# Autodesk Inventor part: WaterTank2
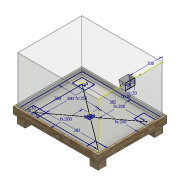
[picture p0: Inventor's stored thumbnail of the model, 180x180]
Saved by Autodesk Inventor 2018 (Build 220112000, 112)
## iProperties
Created: 2018-05
Part Number: WaterTank2
Material: Generic
Document SubType Name: Modeling
Designer: arivu
Density: 1 g/cm^3
Appearance: Default
Author: arivu
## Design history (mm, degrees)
workplane "Work Plane2"
workplane "Work Plane4"
sketch "Sketch1"
  geometry: L1 (-250, 200)-(250, 200); L2 (250, 200)-(250, -200); L3 (250, -200)-(-250, -200); L4 (-250, -200)-(-250, 200); 1 further point
  constraints: 8 end point, 2 parallel, 1 horizontal, 1 perpendicular
  dimensions: "d0" = 250 distance from line of point (0, 0) L4 (= 0.5 x width); "d1" = 250 distance from line of L2 point (0, 0) (= d0); "d2" = 200 distance from line of L3 point (0, 0) (= 0.5 x height); "d3" = 200 distance from line of L1 point (0, 0) (= d2)
extrude "Extrusion1" new body sketch "Sketch1" distance "d4" = 300 (= depth); taper "d5" = 0 deg
sketch "Sketch2"
  geometry: L1 (-250, 200)-(250, 200) reference; L2 (250, -200)-(-250, -200); L3 (-250, -200)-(-250, 200); L4 (-250, 200)-(250, 200); L5 (250, 200)-(250, -200); L6 (262, -212)-(-262, -212); L7 (-262, -212)-(-262, 212); L8 (-262, 212)-(262, 212); L9 (262, 212)-(262, -212); 1 further point
  constraints: 16 end point, 4 parallel, 2 horizontal, 2 perpendicular
  dimensions: "d19" = 12 distance between parallel lines of L5 L9 (computed from osb); "d20" = 12 distance between parallel lines of L2 L6 (computed from osb); "d21" = 12 distance between parallel lines of L7 L3 (computed from osb); "d22" = 12 distance between parallel lines of L8 L1 (computed from osb)
extrude "Extrusion2" new body sketch "Sketch2" distance "d7" = 11 (= osb); taper "d8" = 0 deg
sketch "Sketch3"
  geometry: L1 (250, -200)-(-250, -200) reference; L2 (250, -200)-(200, -200); L3 (200, -200)-(200, -150); L4 (200, -150)-(250, -150); L5 (250, -150)-(250, -200); L6 (-250, 200)-(250, 200) reference; L7 (250, 200)-(200, 200); L8 (200, 200)-(200, 150); L9 (200, 150)-(250, 150); L10 (250, 150)-(250, 200); L11 (-250, 200)-(-200, 200); L12 (-200, 200)-(-200, 150); L13 (-200, 150)-(-250, 150); L14 (-250, 150)-(-250, 200); L15 (-250, -200)-(-200, -200); L16 (-200, -200)-(-200, -150); L17 (-200, -150)-(-250, -150); L18 (-250, -150)-(-250, -200); 1 further point
  constraints: 32 end point, 8 parallel, 4 horizontal, 4 perpendicular
  dimensions: "d9" = 50 distance of L3.end L4.end (= legs); "d10" = 50 distance of L2.end L3.end (= d9); "d11" = 50 distance of L9.end L8.end (= d9); "d12" = 50 distance of L8.end L7.end (= d9); "d13" = 50 distance of L12.end L13.end (= d9); "d14" = 50 distance of L11.end L12.end (= d9); "d15" = 50 distance of L17.end L16.end (= d9); "d16" = 50 distance of L16.end L15.end (= d9)
extrude "Extrusion3" new body sketch "Sketch3" distance "d17" = 50 (= leg_lenght); taper "d18" = 0 deg
sketch "Sketch4"
  geometry: L1 (-262, -212)-(-262, 212) reference; L2 (262, -212)-(-262, -212) reference; L3 (-262, 212)-(262, 212); L4 (262, 212)-(262, -212); L5 (262, -212)-(-262, -212); L6 (-262, -212)-(-262, 212); L7 (-251, 201)-(251, 201); L8 (251, 201)-(251, -201); L9 (251, -201)-(-251, -201); L10 (-251, -201)-(-251, 201); 1 further point
  constraints: 16 end point, 4 parallel, 2 horizontal, 2 perpendicular
  dimensions: "d23" = 11 distance between parallel lines of L7 L3 (= osb); "d25" = 11 distance between parallel lines of L10 L1 (= osb); "d26" = 11 distance between parallel lines of L2 L9 (= osb); "d27" = 11 distance between parallel lines of L4 L8 (= osb)
extrude "Extrusion4" new body sketch "Sketch4" distance "d28" = 33 (= 3 x osb); taper "d29" = 0 deg
sketch "Sketch5"
  geometry: L1 (-200, 150)-(-250, 150) reference; L2 (-10.7, 8.025)-(-200, 150); L3 (250, 150)-(200, 150) reference; L4 (10.7, 8.025)-(200, 150); L5 (-250, -150)-(-200, -150) reference; L6 (-10.7, -8.025)-(-200, -150); L7 (200, -200)-(200, -150) reference; L8 (10.7, -8.025)-(200, -150); L9 (0, 0)-(10.7, 0); L10 (0, 0)-(-10.7, 0); L11 (0, 0)-(0, 17.3); L12 (0, 0)-(0, -17.3); L13 (-10.7, 0)-(-10.7, 17.3); L14 (-10.7, 17.3)-(0, 17.3); L15 (0, 17.3)-(10.7, 17.3); L16 (10.7, 17.3)-(10.7, 0); L17 (10.7, -17.3)-(0, -17.3); L18 (10.7, 0)-(10.7, -17.3); L19 (0, -17.3)-(-10.7, -17.3); L20 (-10.7, -17.3)-(-10.7, 0); L21 (-200, 150)-(-182, 150); L22 (-200, 150)-(-200, -150); L23 (-200, 200)-(-200, 150) reference; L24 (-200, -150)-(200, -150); C1 r 2.5 at (-200, 150); C2 r 2.5 at (-182, 150); C3 r 2.5 at (-200, -150); C4 r 2.5 at (-182, -150); C5 r 2.5 at (182, 150); C6 r 2.5 at (200, 150); C7 r 2.5 at (182, -150); C8 r 2.5 at (200, -150)
  constraints: 38 end point, 8 centre point, 7 point on line, 5 horizontal, 5 perpendicular, 4 vertical, 2 coincident, 1 collinear, 12 other
  dimensions: "d30" = 10.7 distance of L9.start L9.end; "d31" = 10.7 distance of L9.start L10.end; "d32" = 17.3 distance of L9.start L11.end; "d33" = 17.3 distance of L9.start L12.end; "d34" = 5 diameter of C1; "d35" = 18 distance of L21.start L21.end; "d36" = 5 diameter of C2; "d39" = 300 distance of L21.start C3.centre; "d42" = 382 distance of L21.start C5.centre
extrude "Extrusion5" cut sketch "Sketch5" distance "d45" = 1.6; taper "d46" = 0 deg
extrude "Extrusion6" cut sketch "Sketch5" distance "d47" = 1; taper "d48" = 0 deg
workplane "Work Plane1"
workplane "Work Plane3"
sketch "Sketch6"
  geometry: L1 (-497, 347)-(-497, 397) reference; L2 (3, 47)-(3, -3) reference; L3 (-497, 397)-(3, 397); L4 (3, 397)-(3, -3); L5 (3, -3)-(-497, -3); L6 (-497, -3)-(-497, 397); 1 further point
  constraints: 8 end point, 2 parallel, 1 horizontal, 1 perpendicular
extrude "Extrusion7" new body sketch "Sketch6" distance "d49" = 11 (= osb); taper "d50" = 0 deg
sketch "Sketch7"
  geometry: L1 (477, 17)-(399, 17); L2 (399, 17)-(399, 77); L3 (399, 77)-(477, 77); L4 (477, 77)-(477, 17); L5 (447, 47)-(47, 47) reference; L6 (447, 347)-(447, 47) reference; L7 (399, 377)-(477, 377); L8 (477, 377)-(477, 317); L9 (477, 317)-(399, 317); L10 (399, 317)-(399, 377); L11 (17, 77)-(95, 77); L12 (95, 77)-(95, 17); L13 (95, 17)-(17, 17); L14 (17, 17)-(17, 77); L15 (17, 377)-(95, 377); L16 (95, 377)-(95, 317); L17 (95, 317)-(17, 317); L18 (17, 317)-(17, 377); 3 further points
  constraints: 32 end point, 2 horizontal, 2 parallel, 1 perpendicular, 1 vertical, 24 other
  dimensions: "d53" = 30 distance from line of point (447, 47) L4; "d54" = 30 distance from line of L2 point (429, 47); "d55" = 30 distance from line of L3 point (447, 47); "d56" = 30 distance from line of L1 point (429, 47); "d59" = 300 distance of L2.end L7.start; "d62" = 382 distance of L2.end L11.start
extrude "Extrusion8" cut sketch "Sketch7" distance "d65" = 1.5; taper "d66" = 0 deg
sketch "Sketch8"
  geometry: L1 (477, 17)-(399, 17) reference; L2 (477, 77)-(477, 17) reference; L3 (399, 77)-(477, 77) reference; L4 (399, 17)-(399, 77) reference; 1 further point
extrude "Extrusion9" new body sketch "Sketch8" distance "d67" = 1.5; taper "d68" = 0 deg
pattern_linear "Rectangular Pattern1" dims "d71" = 382, "d74" = 300
shell "Shell1" dims "d6" = 3
sketch "Sketch9"
  geometry: 1 further point
sketch "Sketch10"
  geometry: L1 (0, 0)-(297, 0) reference; L2 (297, 197)-(297, 227); L3 (297, 197)-(297, 167); L4 (257, 197)-(297, 197); L5 (297, 197)-(297, 187); L6 (257, 167)-(257, 197); L7 (257, 197)-(257, 227); L8 (297, 197)-(297, 207); L9 (297, 227)-(257, 227); L10 (297, 167)-(257, 167); 6 further points; 2 other entities
  constraints: 18 end point, 2 horizontal, 1 perpendicular, 6 other
  dimensions: "d90" = 200 distance of point (297, 397) L2.start; "d106" = 30 distance of L2.start L2.end; "d107" = 30 distance of L2.start L3.end (= d106); "d108" = 30 distance of L4.start L7.end (= d106); "d109" = 30 distance of L6.start L4.start (= d106); "d110" = 40 distance of L4.start L2.start
extrude "Extrusion12" new body sketch "Sketch10" distance "d96" = 40; taper "d97" = 0 deg
extrude "Extrusion13" new body sketch "Sketch10" distance "d98" = 40; taper "d99" = 0 deg
sketch "Sketch13"
  geometry: L1 (-40, 0)-(-25, 0); L2 (-25, 0)-(-40, 41.164); L3 (-40, 41.164)-(-40, 0); 1 further point
  constraints: 6 end point
  dimensions: "d100" = 15 distance of L1.start L1.end
extrude "Extrusion14" cut sketch "Sketch13" stored distance "d101" = 40; taper "d102" = 0 deg
shell "Shell4" dims "d103" = 1
fillet "Fillet3" dims "d105" = 4
body "Solid1"
body "Solid2"
body "Solid3"
body "Solid4"
body "Solid5"
body "Solid6"
body "Solid8"
body "Solid9"
other parameters: "depth" = 300 [user parameter; used in 1 equation term], "osb" = 11 [user parameter; used in 11 equation terms], "legs" = 50 [user parameter; used in 1 equation term], "leg_lenght" = 50 [user parameter; used in 1 equation term], "d76" = 22, "d77" = 7.8, "d78" = 18.8
